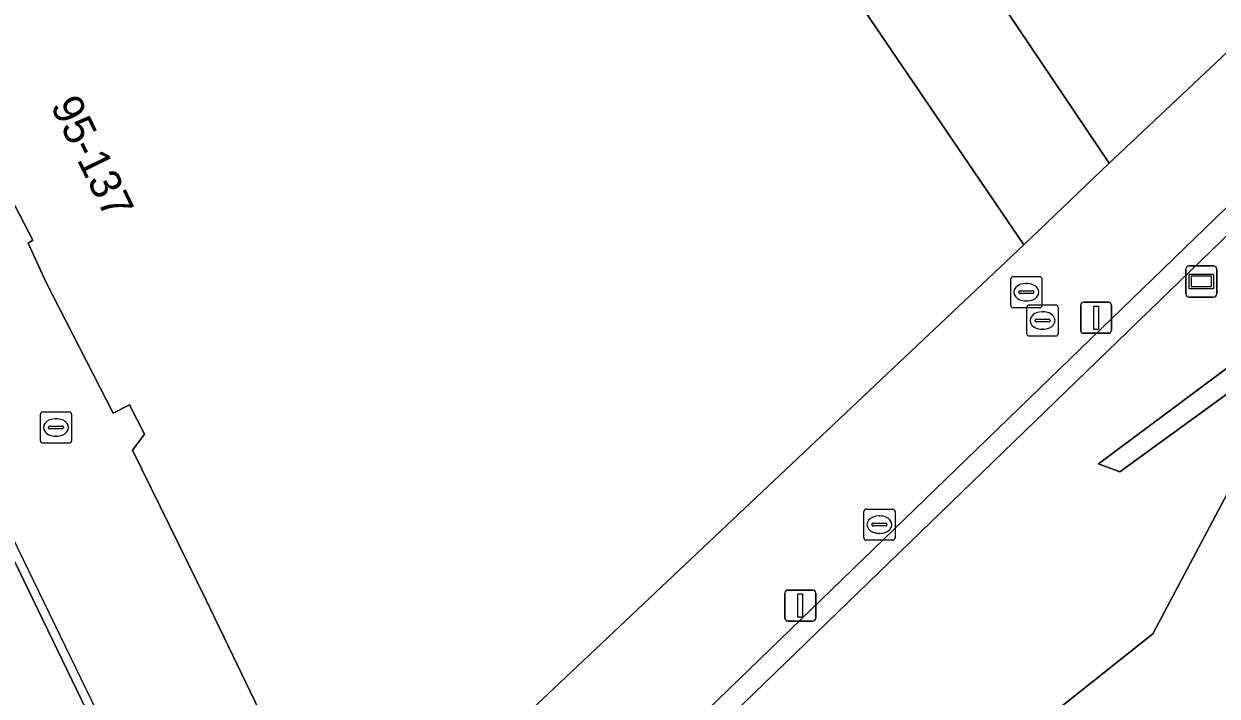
# Model space of a CAD drawing. Extents: x 161087 to 161926, y 382572 to 383873.
# Drawn here: x 161672.56 to 161710.88, y 382927.28 to 382948.89 of the extents above; entities that cross this region are included whole.
import ezdxf

# ---------------------------------------------------------------- set-up
doc = ezdxf.new("R2010")
doc.units = 0
for name, color, linetype in [('IMGEO_Brandkraan', 7, 'Continuous'), ('IMGEO_Erf', 7, 'Continuous'), ('IMGEO_Groenvoorziening', 7, 'Continuous'), ('IMGEO_Informatiebord', 7, 'Continuous'), ('IMGEO_Kolk', 7, 'Continuous'), ('IMGEO_Lichtmast', 7, 'Continuous'), ('IMGEO_Lijnafwatering', 7, 'Continuous'), ('IMGEO_Muur', 7, 'Continuous'), ('IMGEO_Pand', 7, 'Continuous'), ('IMGEO_Pand_nummerreeks', 7, 'Continuous'), ('IMGEO_Rioolput', 7, 'Continuous'), ('IMGEO_Voetgangersgebied_gesloten', 7, 'Continuous'), ('IMGEO_Voetgangersgebied_open', 7, 'Continuous'), ('IMGEO_Voetpad_open', 7, 'Continuous'), ('IMGEO_Walbescherming', 7, 'Continuous'), ('IMGEO_Waterloop', 7, 'Continuous')]:
    doc.layers.add(name, color=color, linetype=linetype)

msp = doc.modelspace()

# ---------------------------------------------------------------- linework, layer by layer
at = {"layer": 'IMGEO_Brandkraan'}
for p, q in [((161673.093, 382935.488), (161673.093, 382936.34)), ((161673.168, 382936.414), (161674.02, 382936.414)), ((161673.581, 382936.194), (161673.606, 382936.194)), ((161674.094, 382936.34), (161674.094, 382935.488)), ((161673.352, 382935.908), (161673.352, 382935.92)), ((161673.79, 382935.871), (161673.392, 382935.871)), ((161673.395, 382935.957), (161673.793, 382935.957)), ((161673.836, 382935.92), (161673.836, 382935.908)), ((161674.02, 382935.414), (161673.168, 382935.414)), ((161673.604, 382935.634), (161673.579, 382935.634))]:
    msp.add_line(p, q, dxfattribs=at)
for points in [[(161673.093, 382935.488), (161673.093, 382936.34)], [(161673.168, 382936.414), (161674.02, 382936.414)], [(161674.094, 382936.34), (161674.094, 382935.488)], [(161674.02, 382935.414), (161673.168, 382935.414)]]:
    msp.add_lwpolyline(points, dxfattribs=at)
for centre, radius, start, end in [((161673.17, 382936.338), 0.0765, 91.552, 178.448), ((161673.17, 382936.338), 0.0765, 91.552, 178.448), ((161674.018, 382936.338), 0.0765, 1.552, 88.448), ((161674.018, 382936.338), 0.0765, 1.552, 88.448), ((161673.392, 382935.917), 0.0403, 85.8775, 175.7526), ((161673.389, 382935.907), 0.0366, 178.938, 274.7102), ((161673.793, 382935.914), 0.043, 264.8664, 352.4533), ((161673.797, 382935.919), 0.0386, 1.7309, 96.639), ((161673.17, 382935.49), 0.0765, 181.552, 268.448), ((161673.17, 382935.49), 0.0765, 181.552, 268.448), ((161674.018, 382935.49), 0.0765, 271.552, 358.448), ((161674.018, 382935.49), 0.0765, 271.552, 358.448)]:
    msp.add_arc(centre, radius, start, end, dxfattribs=at)
for centre, major_axis, ratio, start_param, end_param in [((161673.58, 382935.914), (-0.387, 0.002), 0.722429, 4.712389, 7.853982), ((161673.605, 382935.914), (-0.39, 0.002), 0.717154, 1.570796, 4.712389)]:
    msp.add_ellipse(centre, major_axis=major_axis, ratio=ratio, start_param=start_param, end_param=end_param, dxfattribs=at)
at = {"layer": 'IMGEO_Erf'}
msp.add_lwpolyline([(161688.472, 382972.585), (161684.035, 382979.185), (161679.704, 382985.626), (161675.318, 382992.15), (161672.003, 382997.08), (161668.885, 382995.196), (161672.25, 382988.534), (161675.493, 382981.73), (161678.254, 382976.336), (161679.695, 382973.519), (161679.958, 382973.652), (161682.205, 382969.111), (161682.211, 382969.099), (161683.938, 382969.979), (161685.174, 382970.483), (161704.677, 382941.781), (161707.418, 382944.406)], close=True, dxfattribs=at)
at = {"layer": 'IMGEO_Groenvoorziening'}
for points in [[(161764.784, 383024.938), (161761.545, 383027.521), (161758.426, 383029.994), (161740.45, 382984.512), (161731.348, 382964.654), (161727.347, 382959.466), (161726.694, 382957.106), (161693.352, 382924.798), (161684.407, 382919.024), (161684.56, 382918.709), (161702.106, 382924.334), (161705.33, 382926.507), (161708.818, 382929.281), (161712.224, 382935.704), (161730.015, 382950.57), (161736.475, 382957.843), (161744.027, 382973.55), (161757.459, 383006.424)], [(161707.756, 382934.491), (161707.072, 382934.741), (161713.036, 382939.19), (161712.636, 382940.719), (161723.947, 382949.347), (161730.007, 382954.68), (161730.34, 382954.21), (161713.356, 382940.416), (161713.789, 382938.874)]]:
    msp.add_lwpolyline(points, close=True, dxfattribs=at)
at = {"layer": 'IMGEO_Informatiebord'}
for p, q in [((161709.982, 382941.108), (161710.772, 382941.108)), ((161710.772, 382941.108), (161709.982, 382941.108)), ((161709.882, 382940.208), (161709.882, 382941.008)), ((161709.882, 382941.008), (161709.882, 382940.208)), ((161710.872, 382941.008), (161710.872, 382940.208)), ((161710.872, 382940.208), (161710.872, 382941.008)), ((161710.772, 382940.108), (161709.982, 382940.108)), ((161709.982, 382940.108), (161710.772, 382940.108))]:
    msp.add_line(p, q, dxfattribs=at)
for points in [[(161709.983, 382940.84), (161710.771, 382940.84), (161710.771, 382940.376), (161709.983, 382940.376), (161709.983, 382940.84)], [(161710.048, 382940.775), (161710.048, 382940.441), (161710.706, 382940.441), (161710.706, 382940.775), (161710.048, 382940.775)]]:
    msp.add_lwpolyline(points, dxfattribs=at)
for centre, start, end in [((161709.982, 382941.008), 90, 180), ((161709.982, 382941.008), 90, 180), ((161710.772, 382941.008), 0, 90), ((161710.772, 382941.008), 360, 90), ((161709.982, 382940.208), 180, 270), ((161709.982, 382940.208), 180, 270), ((161710.772, 382940.208), 270, 0), ((161710.772, 382940.208), 270, 0)]:
    msp.add_arc(centre, 0.1, start, end, dxfattribs=at)
at = {"layer": 'IMGEO_Kolk'}
for p, q in [((161704.332, 382940.762), (161705.184, 382940.762)), ((161704.257, 382939.836), (161704.257, 382940.688)), ((161704.745, 382940.542), (161704.77, 382940.542)), ((161705.258, 382940.688), (161705.258, 382939.836)), ((161704.516, 382940.256), (161704.516, 382940.268)), ((161704.954, 382940.219), (161704.556, 382940.219)), ((161704.559, 382940.305), (161704.957, 382940.305)), ((161704.768, 382939.982), (161704.743, 382939.982)), ((161705, 382940.268), (161705, 382940.256)), ((161705.184, 382939.762), (161704.332, 382939.762))]:
    msp.add_line(p, q, dxfattribs=at)
for points in [[(161704.332, 382940.762), (161705.184, 382940.762)], [(161704.257, 382939.836), (161704.257, 382940.688)], [(161705.258, 382940.688), (161705.258, 382939.836)], [(161705.184, 382939.762), (161704.332, 382939.762)]]:
    msp.add_lwpolyline(points, dxfattribs=at)
for centre, radius, start, end in [((161704.334, 382940.686), 0.0765, 91.552, 178.448), ((161704.334, 382940.686), 0.0765, 91.552, 178.448), ((161705.182, 382940.686), 0.0765, 1.552, 88.448), ((161705.182, 382940.686), 0.0765, 1.552, 88.448), ((161704.556, 382940.265), 0.0403, 85.8775, 175.7526), ((161704.553, 382940.255), 0.0366, 178.938, 274.7102), ((161704.957, 382940.262), 0.043, 264.8664, 352.4533), ((161704.961, 382940.267), 0.0386, 1.7309, 96.639), ((161704.334, 382939.838), 0.0765, 181.552, 268.448), ((161704.334, 382939.838), 0.0765, 181.552, 268.448), ((161705.182, 382939.838), 0.0765, 271.552, 358.448), ((161705.182, 382939.838), 0.0765, 271.552, 358.448)]:
    msp.add_arc(centre, radius, start, end, dxfattribs=at)
for centre, major_axis, ratio, start_param, end_param in [((161704.744, 382940.262), (-0.387, 0.002), 0.722429, 4.712389, 7.853982), ((161704.769, 382940.262), (-0.39, 0.002), 0.717154, 1.570796, 4.712389)]:
    msp.add_ellipse(centre, major_axis=major_axis, ratio=ratio, start_param=start_param, end_param=end_param, dxfattribs=at)
at = {"layer": 'IMGEO_Lichtmast'}
for p, q in [((161706.602, 382939.942), (161707.392, 382939.942)), ((161707.392, 382939.942), (161706.602, 382939.942)), ((161706.502, 382939.042), (161706.502, 382939.842)), ((161706.502, 382939.842), (161706.502, 382939.042)), ((161707.492, 382939.842), (161707.492, 382939.042)), ((161707.492, 382939.042), (161707.492, 382939.842)), ((161707.392, 382938.942), (161706.602, 382938.942)), ((161706.602, 382938.942), (161707.392, 382938.942)), ((161697.001, 382929.79), (161697.001, 382930.59)), ((161697.001, 382930.59), (161697.001, 382929.79)), ((161697.101, 382930.69), (161697.891, 382930.69)), ((161697.891, 382930.69), (161697.101, 382930.69)), ((161697.991, 382930.59), (161697.991, 382929.79)), ((161697.991, 382929.79), (161697.991, 382930.59)), ((161697.891, 382929.69), (161697.101, 382929.69)), ((161697.101, 382929.69), (161697.891, 382929.69))]:
    msp.add_line(p, q, dxfattribs=at)
for points in [[(161706.922, 382939.817), (161707.072, 382939.817), (161707.072, 382939.067), (161706.922, 382939.067), (161706.922, 382939.817)], [(161697.421, 382930.565), (161697.571, 382930.565), (161697.571, 382929.815), (161697.421, 382929.815), (161697.421, 382930.565)]]:
    msp.add_lwpolyline(points, dxfattribs=at)
for centre, start, end in [((161706.602, 382939.842), 90, 180), ((161706.602, 382939.842), 90, 180), ((161707.392, 382939.842), 0, 90), ((161707.392, 382939.842), 360, 90), ((161706.602, 382939.042), 180, 270), ((161706.602, 382939.042), 180, 270), ((161707.392, 382939.042), 270, 0), ((161707.392, 382939.042), 270, 0), ((161697.101, 382930.59), 90, 180), ((161697.101, 382930.59), 90, 180), ((161697.891, 382930.59), 0, 90), ((161697.891, 382930.59), 360, 90), ((161697.101, 382929.79), 180, 270), ((161697.101, 382929.79), 180, 270), ((161697.891, 382929.79), 270, 0), ((161697.891, 382929.79), 270, 0)]:
    msp.add_arc(centre, 0.1, start, end, dxfattribs=at)
at = {"layer": 'IMGEO_Lijnafwatering'}
msp.add_lwpolyline([(161675.74, 382925.074), (161663.964, 382949.371)], dxfattribs=at)
at = {"layer": 'IMGEO_Muur'}
for points in [[(161740.681, 382986.664), (161739.867, 382984.771), (161730.734, 382964.893), (161726.799, 382959.834), (161726.106, 382957.452), (161692.853, 382925.234), (161684.124, 382919.605), (161684.007, 382919.846), (161683.751, 382919.765), (161684.3, 382918.626), (161684.56, 382918.709), (161684.407, 382919.024), (161693.352, 382924.798), (161726.694, 382957.106), (161727.347, 382959.466), (161731.348, 382964.654), (161740.45, 382984.512), (161758.426, 383029.994), (161757.921, 383030.385)], [(161713.789, 382938.874), (161713.356, 382940.416), (161730.34, 382954.21), (161730.007, 382954.68), (161723.947, 382949.347), (161712.636, 382940.719), (161713.036, 382939.19), (161707.072, 382934.741), (161707.756, 382934.491)]]:
    msp.add_lwpolyline(points, close=True, dxfattribs=at)
at = {"layer": 'IMGEO_Pand'}
msp.add_lwpolyline([(161702.92, 382982.299), (161688.472, 382972.585), (161707.418, 382944.406), (161720.259, 382956.518), (161718.876, 382958.573), (161704, 382980.687)], close=True, dxfattribs=at)
msp.add_lwpolyline([(161667.318, 382952.236), (161669.565, 382947.802), (161669.867, 382947.263), (161670.126, 382946.786), (161670.293, 382946.845), (161672.848, 382941.939), (161672.698, 382941.84), (161673.272, 382940.591), (161675.427, 382936.374), (161675.953, 382936.643), (161676.434, 382935.699), (161676.054, 382935.188), (161678.417, 382930.369), (161679.977, 382927.119), (161681.214, 382924.572), (161681.324, 382924.633), (161685.137, 382926.533), (161686.757, 382924.859), (161687.867, 382925.913), (161704.677, 382941.781), (161685.174, 382970.483)], dxfattribs=at)
at = {"layer": 'IMGEO_Rioolput'}
for p, q in [((161704.776, 382938.927), (161704.776, 382939.779)), ((161704.851, 382939.853), (161705.703, 382939.853)), ((161705.264, 382939.633), (161705.289, 382939.633)), ((161705.777, 382939.779), (161705.777, 382938.927)), ((161705.035, 382939.347), (161705.035, 382939.359)), ((161705.473, 382939.31), (161705.075, 382939.31)), ((161705.078, 382939.396), (161705.476, 382939.396)), ((161705.519, 382939.359), (161705.519, 382939.347)), ((161705.703, 382938.853), (161704.851, 382938.853)), ((161705.287, 382939.073), (161705.262, 382939.073)), ((161699.538, 382932.366), (161699.538, 382933.218)), ((161699.613, 382933.292), (161700.465, 382933.292)), ((161700.026, 382933.072), (161700.051, 382933.072)), ((161700.539, 382933.218), (161700.539, 382932.366)), ((161699.797, 382932.786), (161699.797, 382932.798)), ((161700.235, 382932.749), (161699.837, 382932.749)), ((161699.84, 382932.835), (161700.238, 382932.835)), ((161700.281, 382932.798), (161700.281, 382932.786)), ((161700.465, 382932.292), (161699.613, 382932.292)), ((161700.049, 382932.512), (161700.024, 382932.512))]:
    msp.add_line(p, q, dxfattribs=at)
for points in [[(161704.776, 382938.927), (161704.776, 382939.779)], [(161704.851, 382939.853), (161705.703, 382939.853)], [(161705.777, 382939.779), (161705.777, 382938.927)], [(161705.703, 382938.853), (161704.851, 382938.853)], [(161699.538, 382932.366), (161699.538, 382933.218)], [(161699.613, 382933.292), (161700.465, 382933.292)], [(161700.539, 382933.218), (161700.539, 382932.366)], [(161700.465, 382932.292), (161699.613, 382932.292)]]:
    msp.add_lwpolyline(points, dxfattribs=at)
for centre, radius, start, end in [((161704.853, 382939.777), 0.0765, 91.552, 178.448), ((161704.853, 382939.777), 0.0765, 91.552, 178.448), ((161705.701, 382939.777), 0.0765, 1.552, 88.448), ((161705.701, 382939.777), 0.0765, 1.552, 88.448), ((161705.075, 382939.356), 0.0403, 85.8775, 175.7526), ((161705.072, 382939.346), 0.0366, 178.938, 274.7102), ((161705.476, 382939.353), 0.043, 264.8664, 352.4533), ((161705.48, 382939.358), 0.0386, 1.7309, 96.639), ((161704.853, 382938.929), 0.0765, 181.552, 268.448), ((161704.853, 382938.929), 0.0765, 181.552, 268.448), ((161705.701, 382938.929), 0.0765, 271.552, 358.448), ((161705.701, 382938.929), 0.0765, 271.552, 358.448), ((161699.615, 382933.216), 0.0765, 91.552, 178.448), ((161699.615, 382933.216), 0.0765, 91.552, 178.448), ((161700.463, 382933.216), 0.0765, 1.552, 88.448), ((161700.463, 382933.216), 0.0765, 1.552, 88.448), ((161699.837, 382932.795), 0.0403, 85.8775, 175.7526), ((161699.834, 382932.785), 0.0366, 178.938, 274.7102), ((161700.238, 382932.792), 0.043, 264.8664, 352.4533), ((161700.242, 382932.797), 0.0386, 1.7309, 96.639), ((161699.615, 382932.368), 0.0765, 181.552, 268.448), ((161699.615, 382932.368), 0.0765, 181.552, 268.448), ((161700.463, 382932.368), 0.0765, 271.552, 358.448), ((161700.463, 382932.368), 0.0765, 271.552, 358.448)]:
    msp.add_arc(centre, radius, start, end, dxfattribs=at)
for centre, major_axis, ratio, start_param, end_param in [((161705.263, 382939.353), (-0.387, 0.002), 0.722429, 4.712389, 7.853982), ((161705.288, 382939.353), (-0.39, 0.002), 0.717154, 1.570796, 4.712389), ((161700.025, 382932.792), (-0.387, 0.002), 0.722429, 4.712389, 7.853982), ((161700.05, 382932.792), (-0.39, 0.002), 0.717154, 1.570796, 4.712389)]:
    msp.add_ellipse(centre, major_axis=major_axis, ratio=ratio, start_param=start_param, end_param=end_param, dxfattribs=at)
at = {"layer": 'IMGEO_Voetgangersgebied_gesloten'}
msp.add_lwpolyline([(161660.568, 382948.962), (161676.869, 382915.408), (161679.531, 382916.561), (161661.239, 382954.441), (161646.183, 382986.769), (161645.23, 382988.71)], dxfattribs=at)
at = {"layer": 'IMGEO_Voetgangersgebied_open'}
msp.add_lwpolyline([(161661.239, 382954.441), (161679.531, 382916.561), (161684.3, 382918.626), (161683.751, 382919.765), (161682.836, 382921.15), (161681.214, 382924.572), (161679.977, 382927.119), (161678.417, 382930.369), (161676.054, 382935.188), (161676.434, 382935.699), (161675.953, 382936.643), (161675.427, 382936.374), (161673.272, 382940.591), (161672.698, 382941.84), (161672.848, 382941.939), (161670.293, 382946.845), (161670.126, 382946.786), (161669.867, 382947.263), (161669.565, 382947.802), (161667.318, 382952.236)], dxfattribs=at)
at = {"layer": 'IMGEO_Voetpad_open'}
msp.add_lwpolyline([(161720.259, 382956.518), (161707.418, 382944.406), (161704.677, 382941.781), (161687.867, 382925.913), (161686.757, 382924.859), (161682.836, 382921.15), (161683.751, 382919.765), (161684.007, 382919.846), (161684.124, 382919.605), (161692.853, 382925.234), (161726.106, 382957.452)], dxfattribs=at)
at = {"layer": 'IMGEO_Walbescherming'}
msp.add_lwpolyline([(161684.56, 382918.709), (161702.106, 382924.334), (161705.33, 382926.507), (161708.818, 382929.281), (161712.224, 382935.704), (161730.015, 382950.57), (161736.475, 382957.843), (161744.027, 382973.55), (161757.459, 383006.424), (161764.784, 383024.938)], dxfattribs=at)
at = {"layer": 'IMGEO_Waterloop'}
msp.add_lwpolyline([(161768.16, 383034.068), (161766.686, 383030.084), (161766.594, 383029.834), (161765.618, 383027.194), (161764.889, 383025.222), (161764.784, 383024.938), (161757.459, 383006.424), (161744.027, 382973.55), (161736.475, 382957.843), (161730.015, 382950.57), (161712.224, 382935.704), (161708.818, 382929.281), (161705.33, 382926.507), (161702.106, 382924.334), (161684.56, 382918.709), (161684.3, 382918.626), (161679.531, 382916.561), (161676.869, 382915.408), (161673.789, 382914.075), (161673.522, 382913.959), (161660.102, 382908.373)], dxfattribs=at)

# ---------------------------------------------------------------- texts
at = {"layer": 'IMGEO_Pand_nummerreeks'}
msp.add_text('95-137', height=1, rotation=296.1095, dxfattribs=at).set_placement((161673.403, 382946.263))

doc.saveas('drawing.dxf')
